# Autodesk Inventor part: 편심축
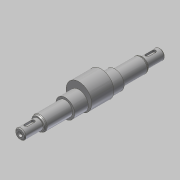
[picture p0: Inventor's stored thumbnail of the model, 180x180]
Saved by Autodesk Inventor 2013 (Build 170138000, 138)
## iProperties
Created: 2019-01
Part Number: 편심축
Material: 강철, 연강
Document SubType Name: Modeling
Designer: mduedu
Density: 1 g/cm^3
Author: mduedu
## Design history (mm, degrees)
sketch "스케치1"
  geometry: L1 (0, 0)-(21, 0); L2 (21, 0)-(21, 6); L3 (21, 6)-(0, 6); L4 (0, 6)-(0, 0); L5 (21, 0)-(53, 0); L6 (53, 0)-(53, 8.5); L7 (53, 8.5)-(21, 8.5); L8 (21, 8.5)-(21, 0); L9 (53, 0)-(111, 0); L10 (111, 0)-(111, 11); L11 (111, 11)-(53, 11); L12 (53, 11)-(53, 0); L13 (82, 11)-(82, 0); L14 (111, 0)-(143, 0); L15 (143, 0)-(143, 8.5); L16 (143, 8.5)-(111, 8.5); L17 (111, 8.5)-(111, 0); L18 (143, 0)-(164, 0); L19 (164, 0)-(164, 6); L20 (164, 6)-(143, 6); L21 (143, 6)-(143, 0)
  constraints: 42 end point, 10 parallel, 5 horizontal, 5 perpendicular, 4 collinear, 2 midpoint
  dimensions: "d3" = 58 distance of L10.end L11.end; "d5" = 12 diameter of L3 L1; "d6" = 17 diameter of L7 L5; "d8" = 22 diameter of L11 L9; "d51" = 164 distance between parallel lines of L4 L19; "d52" = 122 distance between parallel lines of L2 L15; "d53" = 32 distance of L15.end L16.end (derived); "d54" = 32 distance of L6.end L7.end (derived)
revolve "회전1" sketch "스케치1" stored, may be unused: angle "d9" = 90 deg
node "작업 평면3"
sketch "스케치2"
  geometry: C1 r 15 at (0, 4); C2 r 11 at (0, 0); 1 further point
  constraints: 2 centre point, 1 tangent, 1 vertical alignment
  dimensions: "d11" = 4 distance of point (0, 0) C1.centre
extrude "돌출1" join sketch "스케치2" distance "d12" = 26; taper "d13" = 0 deg
node "작업 평면2"
sketch "스케치3" dims "d16" = 12
  geometry: L1 (-4.5, 2)-(3.5, 2); L2 (3.5, 2)-(3.5, -2); L3 (3.5, -2)-(-4.5, -2); L4 (-4.5, -2)-(-4.5, 2); L5 (-10.5, 8.5)-(-10.5, -8.5) reference; 3 further points
  constraints: 8 end point, 2 midpoint, 2 parallel, 2 vertical alignment, 1 horizontal, 1 horizontal alignment, 1 perpendicular, 4 other
  dimensions: "d14" = 4 distance between parallel lines of L3 L1; "d17" = 4 dimension on L5
extrude "돌출2" cut sketch "스케치3" distance "d18" = 2.5; taper "d19" = 0 deg
node "작업 평면4"
chamfer "모따기1" distance "d20" = 1.82; stored, may be unused: second distance "d21" = 2, angle "d22" = 30 deg
chamfer "모따기3" distance "d56" = 1.82; stored, may be unused: second distance "d57" = 2, angle "d58" = 30 deg
fillet "모깎기1" dims "d23" = 2
hole "구멍2" diameter "d39" = 3.242; stored, may be unused: countersink angle "d43" = 60 deg, drill point angle "d45" = 118 deg; dims "d37" = 10, "d38" = 10, "d40" = 8, "d41" = 5.51, "d42" = 2, "d44" = 10
sketch "스케치5"
  geometry: L1 (0, 0)-(2, 0); L2 (2, 0)-(2, 1.621); L3 (0, 2.776)-(0, 0); L4 (0, 2.776)-(2, 1.621); L5 (10, 1.621)-(0, 1.621) reference
  constraints: 8 end point, 1 horizontal, 1 parallel, 1 perpendicular, 1 point on line
  dimensions: "d46" = 2 distance between parallel lines of L2 L3; "d48" = 30 deg angle of L4 L1
revolve "회전2" sketch "스케치5" stored, may be unused: angle "d50" = 90 deg
chamfer "모따기2" distance "d25" = 1; stored, may be unused: second distance "d26" = 2, angle "d27" = 30 deg
node "솔리드1"
mirror "대칭1"
mirror "대칭2"
mirror "대칭3"
other parameters: "d55" = -16
